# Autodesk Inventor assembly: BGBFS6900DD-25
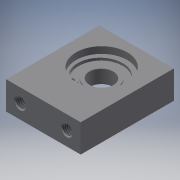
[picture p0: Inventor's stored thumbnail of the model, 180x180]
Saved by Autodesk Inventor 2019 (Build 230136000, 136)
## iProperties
Category: PARTsolutions
Company: MISUMI
Created: 2022-11
Part Number: BGBFS6900DD-25
Catalog Web Link: www.cadenas.de
Description: BGBFB, BGBF, BGBFA, BGBFSA, BGBFS-Bearings with Housings - Bottom Mount - h Configurable
Vendor: MISUMI
Document SubType Name: Assembly
Designer: psAdmin
Manufacturer: MISUMI
Mass: 12.4589 g
Surface Area: 65.3192 cm^2
Volume: 12.4589 cm^3
Density: 1 g/cm^3
Title: BGBFS6900DD-25
Author: Cadenas PARTsolutions
Comments: Bearings with Housings - Bottom Mount - h Configurable
PSOL_IDENT_0: {$CADENAS_DATA/23d-libs/misumi/metric/12_bearing_holders/bgbfb_asmtab.prj},247 {VTYP=3D},{STYP=ASSTA
PSOL_IDENT_1: B},{NB=BGBFS6900DD-25},{LINA=BGBFS6900DD-25},{NN=BGBFB, BGBF, BGBFA, BGBFSA, BGBFS},{DATE=18.09.2019
PSOL_IDENT_2: 08:29:03},{GEOMDATE=09.09.2019 09:38:45},{VERSION=},{LINEID=90},{WBVAR=MATB,MATH,STH,SEAL,HH,ALT1,A
PSOL_IDENT_3: LT2,ALT3},{WBNUMERIC=HH}  {NB=BGBFS6900DD-25},{LINA=BGBFS6900DD-25},{KT=DUMMY},{PN=BGBFS6900DD-25},{
PSOL_IDENT_4: TYPE=BGBFS},{MATB=SS},{MATBALG='S','Steel','SS','Stainless Steel'},{MATH=SUS304},{MATHALG='2017AA','
PSOL_IDENT_5: 2017 Aluminum Alloy','SUS304','304 Stainless Steel'},{STH=-},{STHALG='-','-'},{ARR=304 Stainless Ste
PSOL_IDENT_6: el},{ARR3D=-S},{BN=6900},{SEAL=DD},{SEALALG='ZZ','ZZ(Double Shielded)','VV','VV(Non-Contact Sealed R
PSOL_IDENT_7: ubber Seal)','DD','DD(Contact Sealed Rubber Seal)'},{HH=25},{HHALG=[25:50/1]},{DD=10},{D=22},{DDHH=1
PSOL_IDENT_8: 9},{B=6},{H=40},{H2=15},{L=32},{L1=20},{T=12},{M=M5},{M3D=5},{PITCH=0.8},{ALT1=},{KKC=0},{ALT2=},{MM=
PSOL_IDENT_9: 1.15},{DD2=23},{PPATH=bgbfb/bgbfb_asmtpl.prj},{ALT3=},{ALT1ALG= '', 'Bearing Assembled', '-NA', 'wit
PSOL_IDENT_10: h NA (Bearing not Assembled)' },{ALT2ALG= '','w/o KCC (C2 Chamfer)','-KCC','with KCC (C2 Chamfer)' }
PSOL_IDENT_11: ,{ALT3ALG= '','w/o KKC (C Chamfer)','-KKC','with KKC (C Chamfer)' }
NB: BGBFS6900DD-25
NN: BGBFB, BGBF, BGBFA, BGBFSA, BGBFS
NT: Bearings with Housings - Bottom Mount - h Configurable
NBSYN: $PN.
LINA: BGBFS6900DD-25
CATALOG: Misumi
PN: BGBFS6900DD-25
MATB: Stainless Steel
MATH: 304 Stainless Steel
STH: -
ARR: 304 Stainless Steel
BN: 6900
SEAL: DD(Contact Sealed Rubber Seal)
HH: 25
DD: 10
D: 22
DDHH: 19
B: 6
H: 40
L: 32
L1: 20
T: 12
M: M5
ALT1: Bearing Assembled
ALT2: w/o KCC (C2 Chamfer)
ALT3: w/o KKC (C Chamfer)
SUPPLIER: MISUMI
ARTICLENO: BGBFS6900DD-25
BOMINFO: BGBFS6900DD-25
CREATOR: CADENAS GmbH
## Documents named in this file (4)
- e:\temp\worker_COMMON_18\temp\tmp_5524_252_prE5O\format_0\BGBFS6900DD-25.iam
- e:\temp\worker_COMMON_18\temp\tmp_5524_252_prE5O\format_0\BGBFS6900DD-25-_h.ipt
- e:\temp\worker_COMMON_18\temp\tmp_5524_252_prE5O\format_0\bearing_6900.ipt
- e:\temp\worker_COMMON_18\temp\tmp_5524_252_prE5O\format_0\RRING-C-INT-S-22.ipt
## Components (3 placed, 3 different names)
1. BGBFS6900DD-25-_h:1 — to_bearing_XY@1 <-> to_housing_XY@2, to_bearing_Z@1 <-> to_housing_Z@2, to_bearing_YZ@1 <-> to_housing_YZ@2, to_ring_XY@1 <-> rr_XY@3, to_ring_Z@1 <-> rr_Z@3, to_ring_YZ@1 <-> rr_YZ@3
2. bearing_6900:1 — to_bearing_XY@1 <-> to_housing_XY@2, to_bearing_Z@1 <-> to_housing_Z@2, to_bearing_YZ@1 <-> to_housing_YZ@2
3. RRING-C-INT-S-22:1 — to_ring_XY@1 <-> rr_XY@3, to_ring_Z@1 <-> rr_Z@3, to_ring_YZ@1 <-> rr_YZ@3
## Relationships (6: Mate 4, Angle 2)
- to_bearing_XY@1 <-> to_housing_XY@2 [Mate]: BGBFS6900DD-25-_h:1 ↔ bearing_6900:1
- to_bearing_Z@1 <-> to_housing_Z@2 [Mate]: BGBFS6900DD-25-_h:1 ↔ bearing_6900:1
- to_bearing_YZ@1 <-> to_housing_YZ@2 [Angle]: BGBFS6900DD-25-_h:1 ↔ bearing_6900:1
- to_ring_XY@1 <-> rr_XY@3 [Mate]: BGBFS6900DD-25-_h:1 ↔ RRING-C-INT-S-22:1
- to_ring_Z@1 <-> rr_Z@3 [Mate]: BGBFS6900DD-25-_h:1 ↔ RRING-C-INT-S-22:1
- to_ring_YZ@1 <-> rr_YZ@3 [Angle]: BGBFS6900DD-25-_h:1 ↔ RRING-C-INT-S-22:1
